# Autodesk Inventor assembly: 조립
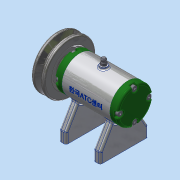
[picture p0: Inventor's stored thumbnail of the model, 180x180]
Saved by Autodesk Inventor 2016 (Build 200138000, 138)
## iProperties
Created: 2018-05
Part Number: 조립
Material: 일반
Document SubType Name: Assembly
Designer: 605-04
Author: 605-04
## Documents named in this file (16)
- C:\Users\605-04\Documents\Inventor\480507V1010\조립.iam
- C:\Users\605-04\Documents\Inventor\480507V1010\1.본체.ipt
- C:\Users\605-04\Documents\Inventor\480507V1010\축.ipt
- C:\Users\605-04\Documents\Inventor\480507V1010\베어링 6002.ipt
- C:\Users\605-04\Documents\Inventor\480507V1010\뒤커버.ipt
- C:\Users\605-04\Documents\Inventor\480507V1010\볼트 M4x12.ipt
- C:\Users\605-04\Documents\Inventor\480507V1010\앞커버.ipt
- C:\Users\605-04\Documents\Inventor\480507V1010\오일 실 15 25 7.ipt
- C:\Users\605-04\Documents\Inventor\480507V1010\키 3x3x12.ipt
- C:\Users\605-04\Documents\Inventor\480507V1010\V벨트풀리.ipt
- C:\Users\605-04\Documents\Inventor\480507V1010\와셔 8x17.ipt
- C:\Users\605-04\Documents\Inventor\480507V1010\스프링와셔 8.ipt
- C:\Users\605-04\Documents\Inventor\480507V1010\너트 M8.ipt
- C:\Users\605-04\Documents\Inventor\480507V1010\니플 M6x0.75.ipt
- C:\Users\605-04\Documents\Inventor\480507V1010\와셔 6x11.5.ipt
- C:\Users\605-04\Documents\Inventor\480507V1010\볼트 M6x8.ipt
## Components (2 placed, 2 different names)
1. 1.본체:1
2. V벨트풀리:1
